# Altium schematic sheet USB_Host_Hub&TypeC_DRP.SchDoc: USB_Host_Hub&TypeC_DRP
size A3; DocumentNumber: MB1272; Revision: A-01; SheetNumber: 6; SheetTotal: 15; Project: STM32MP15-DISCO PI
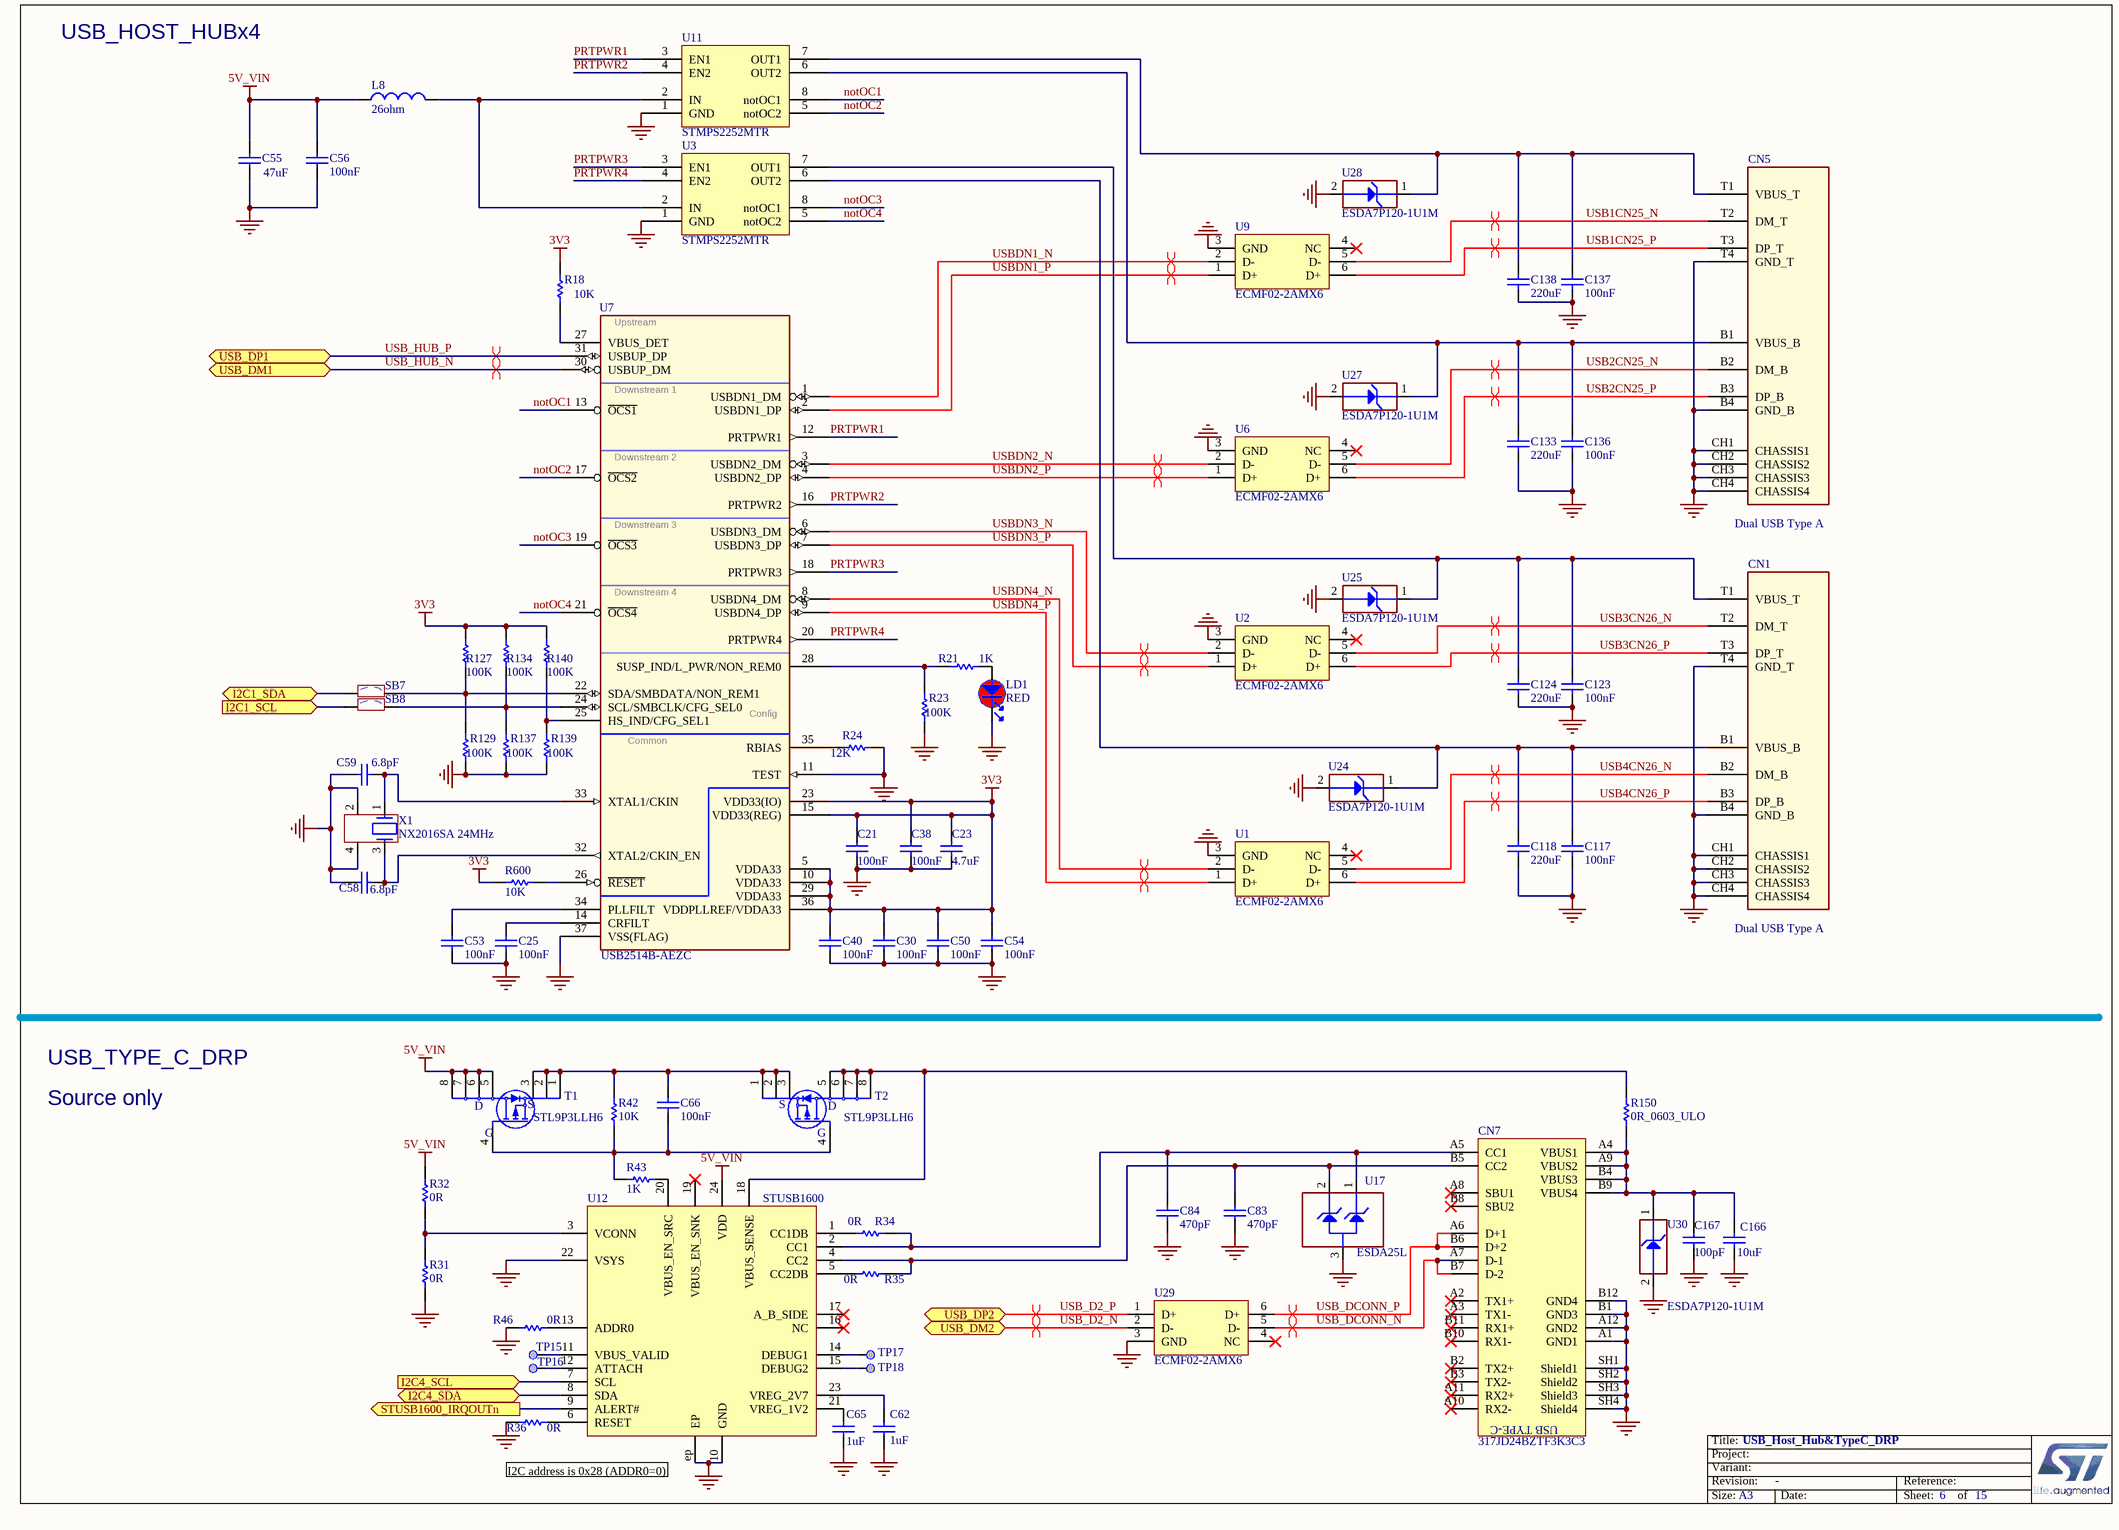
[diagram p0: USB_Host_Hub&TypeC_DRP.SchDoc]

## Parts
C21  value 100nF  [C0402]  (hidden comment: Capacitor)
C23  value 4.7uF  [C0402]  (hidden comment: Capacitor)
C25  value 100nF  [C0402]  (hidden comment: Capacitor)
C30  value 100nF  [C0402]  (hidden comment: Capacitor)
C38  value 100nF  [C0402]  (hidden comment: Capacitor)
C40  value 100nF  [C0402]  (hidden comment: Capacitor)
C50  value 100nF  [C0402]  (hidden comment: Capacitor)
C53  value 100nF  [C0402]  (hidden comment: Capacitor)
C54  value 100nF  [C0402]  (hidden comment: Capacitor)
C55  value 47uF  [C0805]  (hidden comment: Capacitor)
C56  value 100nF  [C0402]  (hidden comment: Capacitor)
C58  value 6.8pF  [C0402]  (hidden comment: Capacitor)
C59  value 6.8pF  [C0402]  (hidden comment: Capacitor)
C62  value 1uF  [C0402]  (hidden comment: Capacitor)
C65  value 1uF  [C0402]  (hidden comment: Capacitor)
C66  value 100nF  [C0402]  (hidden comment: Capacitor)
C83  value 470pF  [C0402]  (hidden comment: Capacitor)
C84  value 470pF  [C0402]  (hidden comment: Capacitor)
C117  value 100nF  [C0402]  (hidden comment: Capacitor)
C118  value 220uF  [C1206_H1P6]  (hidden comment: Capacitor)
C123  value 100nF  [C0402]  (hidden comment: Capacitor)
C124  value 220uF  [C1206_H1P6]  (hidden comment: Capacitor)
C133  value 220uF  [C1206_H1P6]  (hidden comment: Capacitor)
C136  value 100nF  [C0402]  (hidden comment: Capacitor)
C137  value 100nF  [C0402]  (hidden comment: Capacitor)
C138  value 220uF  [C1206_H1P6]  (hidden comment: Capacitor)
C166  value 10uF  [C0805]  (hidden comment: Capacitor)
C167  value 100pF  [C0402]  (hidden comment: Capacitor)
CN1  value Dual USB Type A  [CON_DUAL-USB-TYPE-A_CONEXCON_5600-3081]  (hidden comment: USB_DUAL_TYPEA_5600-3081)
CN5  value Dual USB Type A  [CON_DUAL-USB-TYPE-A_CONEXCON_5600-3081]  (hidden comment: USB_DUAL_TYPEA_5600-3081)
CN7  value 317JD24BZTF3K3C3  [CON_USB-TYPEC_COXOC_317JD24BZTF3K3C3]
L8  value 26ohm  [FIL_0603_H0P65]  (hidden comment: BEAD)
LD1  value RED  [LED_0603_RED]  (hidden comment: LED_red)
R18  value 10K  [R0402]  (hidden comment: Resistor)
R21  value 1K  [R0402]  (hidden comment: Resistor)
R23  value 100K  [R0402]  (hidden comment: Resistor)
R24  value 12K  [R0402]  (hidden comment: Resistor)
R31  value 0R  [R0402]  (hidden comment: Resistor)
R32  value 0R  [R0402]  (hidden comment: Resistor)
R34  value 0R  [R0402]  (hidden comment: Resistor)
R35  value 0R  [R0402]  (hidden comment: Resistor)
R36  value 0R  [R0402]  (hidden comment: Resistor)
R42  value 10K  [R0402]  (hidden comment: Resistor)
R43  value 1K  [R0402]  (hidden comment: Resistor)
R46  value 0R  [R0402]  (hidden comment: Resistor)
R127  value 100K  [R0402]  (hidden comment: Resistor)
R129  value 100K  [R0402]  (hidden comment: Resistor)
R134  value 100K  [R0402]  (hidden comment: Resistor)
R137  value 100K  [R0402]  (hidden comment: Resistor)
R139  value 100K  [R0402]  (hidden comment: Resistor)
R140  value 100K  [R0402]  (hidden comment: Resistor)
R150  value 0R_0603_ULO  [R0603]  (hidden comment: Resistor)
R600  value 10K  [R0402]  (hidden comment: Resistor)
SB7  SB_OFF  [SOLDER-BRIDGE_R0603-0R]  (value not drawn)
SB8  SB_OFF  [SOLDER-BRIDGE_R0603-0R]  (value not drawn)
T1  value STL9P3LLH6  [MOS_POWERFLAT_3P3X3P3_P065]
T2  value STL9P3LLH6  [MOS_POWERFLAT_3P3X3P3_P065]
TP15  Test Point  [TP_SMD_1MM]  (value not drawn)  (no BOM)
TP16  Test Point  [TP_SMD_1MM]  (value not drawn)  (no BOM)
TP17  Test Point  [TP_SMD_1MM]  (value not drawn)  (no BOM)
TP18  Test Point  [TP_SMD_1MM]  (value not drawn)  (no BOM)
U1  value ECMF02-2AMX6  [ESD_QFN-6L_1P7X1P5_P050]  (hidden comment: ​)
U2  value ECMF02-2AMX6  [ESD_QFN-6L_1P7X1P5_P050]  (hidden comment: ​)
U3  STMPS2252MTR  [ICC_SO8_5X4_P127]
U6  value ECMF02-2AMX6  [ESD_QFN-6L_1P7X1P5_P050]  (hidden comment: ​)
U7  USB2514B-AEZC  [ICC_QFN36-EPAD_6X6_P050]
U9  value ECMF02-2AMX6  [ESD_QFN-6L_1P7X1P5_P050]  (hidden comment: ​)
U11  STMPS2252MTR  [ICC_SO8_5X4_P127]
U12  value STUSB1600  [ICC_QFN24-EPAD_4X4_P050]  (hidden comment: ​Symbol correction needed ?)
U17  value ESDA25L  [ESD_SOT23]  (hidden comment: New schematic symbol : correction 2 diodes instead of one)
U24  value ESDA7P120-1U1M  [ESD_QFN1610_2N_1K_2A]  (hidden comment: ​Footprint needed DFN105P160X60-2N)
U25  value ESDA7P120-1U1M  [ESD_QFN1610_2N_1K_2A]  (hidden comment: ​Footprint needed DFN105P160X60-2N)
U27  value ESDA7P120-1U1M  [ESD_QFN1610_2N_1K_2A]  (hidden comment: ​Footprint needed DFN105P160X60-2N)
U28  value ESDA7P120-1U1M  [ESD_QFN1610_2N_1K_2A]  (hidden comment: ​Footprint needed DFN105P160X60-2N)
U29  value ECMF02-2AMX6  [ESD_QFN-6L_1P7X1P5_P050]  (hidden comment: ​)
U30  value ESDA7P120-1U1M  [ESD_QFN1610_2N_1K_2A]  (hidden comment: ​Footprint needed DFN105P160X60-2N)
X1  value NX2016SA 24MHz  [CRY_NX2016SA_4P]  (hidden comment: XTAL_4_PINS)

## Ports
I2C1_SCL (in), I2C1_SDA (bidir), I2C4_SCL (in), I2C4_SDA (bidir), STUSB1600_IRQOUTn (out), USB_DM1 (bidir), USB_DM2 (bidir), USB_DP1 (bidir), USB_DP2 (bidir)

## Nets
3V3: C21.2 C23.2 C30.2 C38.2 C40.2 C50.2 C54.2 R18.2 R127.2 R134.2 R140.2 R600.1 U7.5(VDDA33) U7.10(VDDA33) U7.15(VDD33(REG)) U7.23(VDD33(IO)) U7.29(VDDA33) U7.36(VDDPLLREF/VDDA33)
5V_VIN: C55.2 C56.2 L8.1 R32.2 T1.5(D) T1.6(D) T1.7(D) T1.8(D) U12.24(VDD)
GND: C21.1 C23.1 C25.1 C30.1 C38.1 C40.1 C50.1 C53.1 C54.1 C55.1 C56.1 C58.1 C59.1 C62.1 C65.1 C83.1 C84.1 C117.1 C118.1 C123.1 C124.1 C133.1 C136.1 C137.1 C138.1 C166.1 C167.1 CN1.B4(GND_B) CN1.CH1(CHASSIS1) CN1.CH2(CHASSIS2) CN1.CH3(CHASSIS3) CN1.CH4(CHASSIS4) CN1.T4(GND_T) CN5.B4(GND_B) CN5.CH1(CHASSIS1) CN5.CH2(CHASSIS2) CN5.CH3(CHASSIS3) CN5.CH4(CHASSIS4) CN5.T4(GND_T) CN7.A1(GND1) CN7.A12(GND2) CN7.B1(GND3) CN7.B12(GND4) CN7.SH1(Shield1) CN7.SH2(Shield2) CN7.SH3(Shield3) CN7.SH4(Shield4) LD1.2 R23.1 R24.1 R31.1 R36.1 R46.1 R129.1 R137.1 R139.1 U1.3(GND) U2.3(GND) U3.1(GND) U6.3(GND) U7.11(TEST) U7.37(VSS(FLAG)) U9.3(GND) U11.1(GND) U12.10(GND) U12.22(VSYS) U12.ep(EP) U17.3(GND) U24.2(GND) U25.2(GND) U27.2(GND) U28.2(GND) U29.3(GND) U30.2(GND) X1.2 X1.4
I2C1_SCL: SB8.1 ; port I2C1_SCL
I2C1_SDA: SB7.1 ; port I2C1_SDA
I2C4_SCL: U12.7(SCL) ; port I2C4_SCL
I2C4_SDA: U12.8(SDA) ; port I2C4_SDA
notOC1: U7.13(~{OCS1}) U11.8(notOC1)
notOC2: U7.17(~{OCS2}) U11.5(notOC2)
notOC3: U3.8(notOC1) U7.19(~{OCS3})
notOC4: U3.5(notOC2) U7.21(~{OCS4})
PRTPWR1: U7.12(PRTPWR1) U11.3(EN1)
PRTPWR2: U7.16(PRTPWR2) U11.4(EN2)
PRTPWR3: U3.3(EN1) U7.18(PRTPWR3)
PRTPWR4: U3.4(EN2) U7.20(PRTPWR4)
STUSB1600_IRQOUTn: U12.9(ALERT#) ; port STUSB1600_IRQOUTn
USB1CN25_N: CN5.T2(DM_T) U9.5(D-)
USB1CN25_P: CN5.T3(DP_T) U9.6(D+)
USB2CN25_N: CN5.B2(DM_B) U6.5(D-)
USB2CN25_P: CN5.B3(DP_B) U6.6(D+)
USB3CN26_N: CN1.T2(DM_T) U2.5(D-)
USB3CN26_P: CN1.T3(DP_T) U2.6(D+)
USB4CN26_N: CN1.B2(DM_B) U1.5(D-)
USB4CN26_P: CN1.B3(DP_B) U1.6(D+)
USB_D2_N: U29.2(D-) ; port USB_DM2
USB_D2_P: U29.1(D+) ; port USB_DP2
USB_DCONN_N: CN7.A7(D-1) CN7.B7(D-2) U29.5(D-)
USB_DCONN_P: CN7.A6(D+1) CN7.B6(D+2) U29.6(D+)
USB_HUB_N: U7.30(USBUP_DM) ; port USB_DM1
USB_HUB_P: U7.31(USBUP_DP) ; port USB_DP1
USBDN1_N: U7.1(USBDN1_DM) U9.2(D-)
USBDN1_P: U7.2(USBDN1_DP) U9.1(D+)
USBDN2_N: U6.2(D-) U7.3(USBDN2_DM)
USBDN2_P: U6.1(D+) U7.4(USBDN2_DP)
USBDN3_N: U2.2(D-) U7.6(USBDN3_DM)
USBDN3_P: U2.1(D+) U7.7(USBDN3_DP)
USBDN4_N: U1.2(D-) U7.8(USBDN4_DM)
USBDN4_P: U1.1(D+) U7.9(USBDN4_DP)
NetC25_2: C25.2 U7.14(CRFILT)
NetC53_2: C53.2 U7.34(PLLFILT)
NetC58_2: C58.2 U7.32(XTAL2/CKIN_EN) X1.3
NetC59_2: C59.2 U7.33(XTAL1/CKIN) X1.1
NetC62_2: C62.2 U12.23(VREG_2V7)
NetC65_2: C65.2 U12.21(VREG_1V2)
NetC66_1: C66.1 R42.1 R43.1 T1.4(G) T2.4(G)
NetC66_2: C66.2 R42.2 T1.1(S) T1.2(S) T1.3(S) T2.1(S) T2.2(S) T2.3(S)
NetC83_2: C83.2 CN7.B5(CC2) R35.2 U12.4(CC2) U17.2(IO2)
NetC84_2: C84.2 CN7.A5(CC1) R34.2 U12.2(CC1) U17.1(IO1)
NetC117_2: C117.2 C118.2 CN1.B1(VBUS_B) U3.6(OUT2) U24.1(IO1)
NetC123_2: C123.2 C124.2 CN1.T1(VBUS_T) U3.7(OUT1) U25.1(IO1)
NetC133_2: C133.2 C136.2 CN5.B1(VBUS_B) U11.6(OUT2) U27.1(IO1)
NetC137_2: C137.2 C138.2 CN5.T1(VBUS_T) U11.7(OUT1) U28.1(IO1)
NetC166_2: C166.2 C167.2 CN7.A4(VBUS1) CN7.A9(VBUS2) CN7.B4(VBUS3) CN7.B9(VBUS4) R150.1 U30.1(IO1)
NetL8_2: L8.2 U3.2(IN) U11.2(IN)
NetLD1_1: LD1.1 R21.1
NetR18_1: R18.1 U7.27(VBUS_DET)
NetR21_2: R21.2 R23.2 U7.28(SUSP_IND/L_PWR/NON_REM0)
NetR24_2: R24.2 U7.35(RBIAS)
NetR31_2: R31.2 R32.1 U12.3(VCONN)
NetR34_1: R34.1 U12.1(CC1DB)
NetR35_1: R35.1 U12.5(CC2DB)
NetR36_2: R36.2 U12.6(RESET)
NetR43_2: R43.2 U12.20(VBUS_EN_SRC)
NetR46_2: R46.2 U12.13(ADDR0)
NetR127_1: R127.1 R129.2 SB7.2 U7.22(SDA/SMBDATA/NON_REM1)
NetR134_1: R134.1 R137.2 SB8.2 U7.24(SCL/SMBCLK/CFG_SEL0)
NetR139_2: R139.2 R140.1 U7.25(HS_IND/CFG_SEL1)
NetR150_2: R150.2 T2.5(D) T2.6(D) T2.7(D) T2.8(D) U12.18(VBUS_SENSE)
NetR600_2: R600.2 U7.26(~{RESET})
NetTP15_1: TP15.1 U12.11(VBUS_VALID)
NetTP16_1: TP16.1 U12.12(ATTACH)
NetTP17_1: TP17.1 U12.14(DEBUG1)
NetTP18_1: TP18.1 U12.15(DEBUG2)

Not connected (* = marked no-connect by the designer): CN7 A2(TX1+)* A3(TX1-)* A8(SBU1)* A10(RX2-)* A11(RX2+)* B2(TX2+)* B3(TX2-)* B8(SBU2)* B10(RX1-)* B11(RX1+)*; U1 4(NC)*; U2 4(NC)*; U6 4(NC)*; U9 4(NC)*; U12 16(NC)* 17(A_B_SIDE)* 19(VBUS_EN_SNK)*; U29 4(NC)*

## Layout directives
differential pair: USB1CN25_N, USB1CN25_P, USB2CN25_N, USB2CN25_P, USB3CN26_N, USB3CN26_P, USB4CN26_N, USB4CN26_P, USB_D2_N, USB_D2_P, USB_DCONN_N, USB_DCONN_P, USB_HUB_N, USB_HUB_P, USBDN1_N, USBDN1_P, USBDN2_N, USBDN2_P, USBDN3_N, USBDN3_P, USBDN4_N, USBDN4_P

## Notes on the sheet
- USB_HOST_HUBx4
- USB_TYPE_C_DRP
- Source only
- I2C address is 0x28 (ADDR0=0)

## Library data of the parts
C21 C25 C30 C38 C40 C50 C53 C54 C56 C66 C117 C123 C136 C137 = MCD-00102: Capacitor, MLCC, 100nF, 16V, X7R, 10%, 0402, T=0,5mm; Manufacturer_Part_Number: CC0402KRX7R7BB104; Manufacturer: YAGEO; Alternate_Manufacturer: MURATA; Alternate_Manufacturer_Part_Number: GCM155R71C104KA55D; Provided_By: SUBCO; Initial_Board_Reference: MB1262
C23 = MCD-01356: Capacitor, MLCC, 4.7uF, 6V3, X5R, 20%, 0402, T=0,5mm; Manufacturer_Part_Number: GRM155R60J475ME47; Manufacturer: MURATA; Provided_By: SUBCO
C55 = MCD-00204: Capacitor, MLCC, 47uF, 10V, X5R, 20%, 0805, T=1,25mm; Manufacturer_Part_Number: GRM21BR61A476ME15K; Manufacturer: MURATA; Provided_By: SUBCO; ECCN_US: EAR99; ECCN_EU: NEC
C58 C59 = MCD-00674: Capacitor, MLCC, 6.8pF, 50V, NPO, +-0.25pF, 0402, T=0.5mm; Manufacturer_Part_Number: CC0402CRNPO9BN6R8; Manufacturer: YAGEO; Provided_By: SUBCO
C62 C65 = MCD-00095: Capacitor, MLCC, 1uF, 6V3, X5R, 10%, 0402, T=0,5mm; Manufacturer_Part_Number: GRM155R61E105KA12; Manufacturer: MURATA; Alternate_Manufacturer_Part_Number: GRM155R60J105KE19; ECCN_US: EAR99; ECCN_EU: NEC; Provided_By: SUBCO; Initial_Board_Reference: MB1262
C83 C84 = MCD-00724: Capacitor, MLCC, 470pF, 50V, NPO, 5%, 0402, T=0,5mm; Manufacturer_Part_Number: CC0402JRNPO9BN471; Manufacturer: YAGEO; Provided_By: SUBCO; Initial_Board_Reference: MB1271
C118 C124 C133 C138 = MCD-00104: Capacitor, MLCC, 220uF, 6V3, X5R, 20%, 1206, T=1,6mm; Manufacturer_Part_Number: GRM31CR60J227ME11; Manufacturer: MURATA; ECCN_US: EAR99; ECCN_EU: NEC; Provided_By: SUBCO; Initial_Board_Reference: MB1262
C166 = MCD-00014: Capacitor, MLCC, 10uF, 25V, X5R, 10%, 0805, T=0,85mm; Manufacturer_Part_Number: CC0805KRX5R8BB106; Manufacturer: YAGEO; Provided_By: SUBCO; Initial_Board_Reference: MB1274
C167 = MCD-00205: Capacitor, MLCC, 100pF, 50V, NPO, 5%, 0402, T=0,5mm; Manufacturer_Part_Number: CC0402JRNPO9BN101; Manufacturer: YAGEO; Provided_By: SUBCO
CN1 CN5 = MCD-00109: USB-Receptacle,Dual-Type-A, RA, TH, Height 15.5mm; Manufacturer: CONEXCON; Part_Type: Connector; Provided_By: SUBCO; Initial_Board_Reference: MB1262
CN7 = MCD-01108: USB tyce C certified receptacle for 1.6mm pcb height; Part_Type: Connector; Manufacturer: CHANT SINCERE (COXOC); ECCN_US: NA; Provided_By: SUBCO; Initial_Board_Reference: MB1272
L8 = MCD-00305: Bead,26R at 100Mhz,6A,0603; Manufacturer_Part_Number: BLM18KG260TN1; Manufacturer: MURATA; Part_Type: Inductor; Provided_By: SUBCO; Initial_Board_Reference: MB1272
LD1 = MCD-00049: LED, Red, 0603; Manufacturer_Part_Number: 19-213-R6C-AP1Q2B/3T; Manufacturer: EVERLIGHT; Part_Type: Display; ECCN_US: EAR99; ECCN_EU: NEC; Provided_By: SUBCO; Initial_Board_Reference: MB1274
R18 R42 R600 = MCD-00053: Resistor,10K,0402,1%,1/16W; Manufacturer_Part_Number: RC0402FR-0710KL; Manufacturer: YAGEO; Provided_By: SUBCO; Initial_Board_Reference: MB1274
R21 R43 = MCD-00061: Resistor,1K,0402,1%,1/16W; Manufacturer_Part_Number: RC0402FR-071KL; Manufacturer: YAGEO; Provided_By: SUBCO; Initial_Board_Reference: MB1274
R23 R127 R129 R134 R137 R139 R140 = MCD-00059: Resistor,100K,0402,1%,1/16W; Manufacturer_Part_Number: RC0402FR-07100KL; Manufacturer: YAGEO; Alternate_Manufacturer_Part_Number: RT0402FRE07100KL; Provided_By: SUBCO; Initial_Board_Reference: MB1274
R24 = MCD-00187: Resistor,12K,0402,1%,1/16W; Manufacturer_Part_Number: RC0402FR-0712KL; Manufacturer: YAGEO; Provided_By: SUBCO
R31 R32 R34-R36 R46 = MCD-00052: Resistor,0R,0402,5%,1/16W; Manufacturer_Part_Number: RC0402JR-070RL; Manufacturer: YAGEO; Provided_By: SUBCO; Initial_Board_Reference: MB1274
R150 = MCD-00181: Resistor,0R,0603,ULO; Manufacturer_Part_Number: PMR03EZPJ000; Manufacturer: ROHM; Provided_By: SUBCO
SB7 SB8 = MCD-00072: Solder Bridge OFF; Part_Type: Mechanical; Manufacturer: YAGEO; Manufacturer_Part_Number: RC0603JR-070RL; Provided_By: SUBCO; Initial_Board_Reference: MB1274
T1 T2 = MCD-01126: Power Mosfet, P-channel,VDS -30V,RDS 12mohm typ,ID -9A; Part_Type: IC; Manufacturer: STMICROELECTRONICS; ECCN_US: EAR99; ECCN_EU: NEC; Provided_By: SUBCO with ST control; Initial_Board_Reference: MB1272
TP15-TP18 = MCD-00074: Test Point 1mm; Part_Type: Mechanical; Initial_Board_Reference: MB1274
U1 U2 U6 U9 U29 = MCD-00649: Common mode filter with ESD protection for USB 2.0 interface; Part_Type: Diode; Manufacturer: STMICROELECTRONICS; BMS_Part_Number: 9151138; ECCN_US: EAR99; ECCN_EU: NEC; Provided_By: SUBCO with ST control; Initial_Board_Reference: MB1248
U3 U11 = MCD-00123: IC,Dual-Channel-Power-Switch,500mA,100mR,SO8; Manufacturer: STMICROELECTRONICS; BMS_Part_Number: 9159012; ECCN_US: EAR99; ECCN_EU: NEC; Provided_By: SUBCO with ST control; Initial_Board_Reference: MB1262
U7 = MCD-00145: USB HUB 2,0 Controller; Manufacturer: MICROCHIP; Part_Type: IC; ECCN_US: EAR99; ECCN_EU: NEC; Provided_By: SUBCO; Initial_Board_Reference: MB1262
U12 = MCD-00676: USB Type-C controller with VCONN switch; Part_Type: IC; Manufacturer_Part_Number: STUSB1600AQTR; Manufacturer: STMICROELECTRONICS; BMS_Part_Number: 9158053; Provided_By: SUBCO with ST control; Initial_Board_Reference: MB1272
U17 = MCD-01125: DUAL TRANSIL ARRAY FOR ESD PROTECTION; Part_Type: Diode; Manufacturer: STMICROELECTRONICS; BMS_Part_Number: 9151131; ECCN_US: EAR99; ECCN_EU: NEC; Provided_By: SUBCO with ST control; Initial_Board_Reference: MB1272
U24 U25 U27 U28 U30 = MCD-01026: High power transient voltage suppressor; Part_Type: Diode; Manufacturer: STMICROELECTRONICS; BMS_Part_Number: 9179046; ECCN_US: EAR99; ECCN_EU: NEC; Provided_By: SUBCO with ST control; Initial_Board_Reference: MB1378
X1 = MCD-01036: Crystal 24MHz, 6pF, +-20ppm, 80ohms max, SMD; Part_Type: Crystal_Osc; Manufacturer_Part_Number: NX2016SA 24MHz EXS00A-CS10820; Manufacturer: NDK; BMS_Part_Number: 9157045; Provided_By: SUBCO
